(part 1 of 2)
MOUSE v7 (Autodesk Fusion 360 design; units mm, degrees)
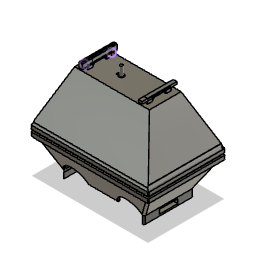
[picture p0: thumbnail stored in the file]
work_plane "WorkPlane1" AlongDistance 0
sketch "Sketch1" plane through (0, 0, 0) normal (0, 1, 0) x axis (1, 0, 0)
work_plane "WorkPlane1" AlongDistance 0
sketch "Sketch1" plane through (0, 0, 0) normal (0, 1, 0) x axis (1, 0, 0)
  line L1 (-450, 0) -> (0, 0)
  line L2 (0, 275) -> (0, 0)
  line L3 (-450, 0) -> (0, 0)
  line L4 (-450, 275) -> (-450, 0)
  line L5 (0, 275) -> (-450, 275)
  line L6 (0, 0) -> (0, 275)
  point P1 (0, 0)
  point P2 (0, 0)
  point P4 (0, 0)
  point P6 (0, 0)
  point P3 (-450, 0)
  point P5 (0, 275)
  coincident P1 P2
  horizontal L1
  coincident P1 P4
  perpendicular L1 L2
  horizontal L3
  vertical L4
  horizontal L5
  vertical L6
  coincident P1 P6
  dimension "d3" distance P2 P3 = 450
  dimension "d4" distance P4 P5 = 275
extrude "Extrude1" new body sketch "Sketch1" along normal blind 10
work_plane "WorkPlane2" AlongDistance 150
sketch "Sketch2" plane through (0, 160, 0) normal (0, 1, 0) x axis (1, 0, 0)
  line L1 (-450, 275) -> (0, 275)
  line L2 (-450, 0) -> (-450, 275)
  line L3 (0, 137.5) -> (-450, 137.5)
  line L4 (-225, 0) -> (-225, 275)
  line L5 (-537.5, -62.5) -> (87.5, -62.5)
  line L6 (-537.5, 337.5) -> (-537.5, -62.5)
  line L7 (87.5, 337.5) -> (-537.5, 337.5)
  line L8 (87.5, -62.5) -> (87.5, 337.5)
  line L9 (-537.5, 337.5) -> (87.5, -62.5)
  line L10 (87.5, 337.5) -> (-537.5, -62.5)
  point P5 (-450, 137.5)
  point P7 (-225, 275)
  point P13 (-225, 137.5)
  point P11 (-537.5, 337.5)
  point P12 (87.5, 337.5)
  point P10 (-537.5, -62.5)
  horizontal L1
  perpendicular L1 L2
  midpoint L2 P5
  perpendicular L2 L3
  midpoint L1 P7
  perpendicular L3 L4
  horizontal L5
  perpendicular L5 L6
  parallel L5 L7
  parallel L6 L8
  coincident L9 P13
  coincident L10 P13
  midpoint L4 P13
  dimension "d8" distance P11 P12 = 625
  dimension "d9" distance P10 P11 = 400
loft "Loft1" sketch "Sketch2"
sketch "Sketch3" plane through (0, 160, 0) normal (0, 1, 0) x axis (-1, 0, 0)
  line L1 (-87.5, -337.5) -> (-87.5, 62.5)
  line L2 (537.5, -337.5) -> (-87.5, -337.5)
  line L3 (537.5, 62.5) -> (537.5, -337.5)
  line L4 (-87.5, 62.5) -> (537.5, 62.5)
  line L5 (537.5, 62.5) -> (-87.5, 62.5)
  line L6 (537.5, 62.5) -> (537.5, -337.5)
  line L7 (-87.5, -137.5) -> (537.5, -137.5)
  line L8 (225, -337.5) -> (225, 62.5)
  line L9 (550, 75) -> (-100, 75)
  line L10 (550, -350) -> (550, 75)
  line L11 (-100, -350) -> (550, -350)
  line L12 (-100, 75) -> (-100, -350)
  line L13 (550, -350) -> (-100, 75)
  line L14 (-100, -350) -> (550, 75)
  point P2 (-87.5, 62.5)
  point P6 (-87.5, 62.5)
  point P5 (537.5, 62.5)
  point P7 (537.5, 62.5)
  point P4 (537.5, -337.5)
  point P8 (537.5, -337.5)
  point P9 (537.5, -137.5)
  point P10 (-87.5, -137.5)
  point P11 (225, 62.5)
  point P12 (225, -337.5)
  point P17 (225, -137.5)
  point P15 (550, -350)
  point P16 (-100, -350)
  point P14 (550, 75)
  coincident P2 P6
  coincident P5 P7
  coincident P4 P8
  midpoint L6 P9
  midpoint L1 P10
  midpoint L5 P11
  midpoint L2 P12
  horizontal L9
  perpendicular L9 L10
  parallel L9 L11
  parallel L10 L12
  coincident L13 P17
  coincident L14 P17
  midpoint L8 P17
  dimension "d10" distance P15 P16 = 650
  dimension "d11" distance P14 P15 = 425
extrude "Extrude2" new body sketch "Sketch3" profile of L1 L2 L3 L4 L5 L6 L9 L10 L11 L12 along normal blind 20
extrude "Extrude3" add of existing geometry blind 25
extrude "Extrude4" add of existing geometry blind 25
extrude "Extrude5" add of existing geometry blind 25
extrude "Extrude6" add of existing geometry blind 25
shell "Shell1" innerThickness 10
work_plane "WorkPlane3" AlongDistance 0
sketch "Sketch4" plane through (0, 0, -275) normal (0, 0, -1) x axis (-1, 0, 0)
  line L1 (450, 0) -> (0, 0)
  line L2 (375, 0) -> (225, 0)
  line L3 (75, 0) -> (225, 0)
  circle C1 centre (375, 0) radius 67.5
  circle C2 centre (75, 0) radius 67.5
  point P1 (0, 0)
  point P2 (0, 0)
  point P4 (225, 0)
  point P5 (375, 0)
  point P6 (375, 0)
  point P7 (75, 0)
  point P8 (75, 0)
  coincident P1 P2
  horizontal L1
  midpoint L1 P4
  parallel L1 L2
  coincident P5 P6
  parallel L1 L3
  coincident P7 P8
  dimension "d24" distance P4 P5 = 150
  dimension "d25" diameter C1 = 135
  dimension "d26" distance P4 P7 = 150
  dimension "d27" diameter C2 = 135
extrude "Extrude7" cut sketch "Sketch4" distance -330
extrude "Extrude8" cut of existing geometry blind -130
extrude "Extrude9" add of existing geometry blind 30
sketch "Sketch5" plane through (0, 0, 0) normal (1, 0, 0) x axis (0, 0, -1)
  line L1 (275, 10) -> (275, -30)
  line L2 (0, 10) -> (275, 10)
  line L3 (0, -30) -> (0, 10)
  line L4 (275, -30) -> (0, -30)
  line L5 (197.5, -30) -> (137.5, -30)
  line L6 (77.5, -30) -> (137.5, -30)
  line L7 (197.5, 10) -> (197.5, -30)
  line L8 (77.5, 10) -> (77.5, -30)
  line L9 (197.5, 10) -> (77.5, 10)
  point P6 (137.5, -30)
  point P9 (197.5, 10)
  point P10 (77.5, 10)
  point P7 (197.5, -30)
  point P8 (77.5, -30)
  midpoint L4 P6
  parallel L4 L5
  parallel L4 L6
  coincident L2 P9
  perpendicular L2 L7
  coincident L2 P10
  perpendicular L2 L8
  dimension "d34" distance P6 P7 = 60
  dimension "d35" distance P6 P8 = 60
extrude "Extrude10" add sketch "Sketch5" profile of L2 L4 L5 L6 L7 L8 L9 against normal blind 30
sketch "Sketch6" plane through (-450, 0, 0) normal (-1, 0, 0) x axis (0, 0, 1)
  line L1 (0, 10) -> (0, -30)
  line L2 (-275, 10) -> (0, 10)
  line L3 (-275, -30) -> (-275, 10)
  line L4 (0, -30) -> (-275, -30)
  line L5 (0, -30) -> (-275, -30)
  line L6 (-77.5, -30) -> (-137.5, -30)
  line L7 (-197.5, -30) -> (-137.5, -30)
  line L8 (-197.5, -30) -> (-77.5, -30)
  line L9 (-197.5, 10) -> (-197.5, -30)
  line L10 (-77.5, 10) -> (-197.5, 10)
  line L11 (-77.5, -30) -> (-77.5, 10)
  point P5 (-275, -30)
  point P6 (-275, -30)
  point P2 (0, -30)
  point P7 (0, -30)
  point P8 (-137.5, -30)
  point P12 (-197.5, 10)
  point P9 (-77.5, -30)
  point P10 (-197.5, -30)
  coincident P5 P6
  coincident P2 P7
  midpoint L5 P8
  perpendicular L1 L6
  parallel L5 L7
  horizontal L8
  vertical L9
  horizontal L10
  vertical L11
  coincident L2 P12
  dimension "d38" distance P8 P9 = 60
  dimension "d39" distance P8 P10 = 60
extrude "Extrude11" add sketch "Sketch6" profile of L2 L4 L5 L6 L7 L8 L9 L10 L11 against normal blind 40
extrude "Extrude12" add of existing geometry blind 10
sketch "Sketch7" plane through (0, 0, 0) normal (1, 0, 0) x axis (0, 0, -1)
  line L1 (275, -30) -> (0, -30)
  line L2 (275, 10) -> (275, -30)
  line L3 (0, 10) -> (275, 10)
  line L4 (0, -30) -> (0, 10)
  line L5 (187.5, -30) -> (137.5, -30)
  line L6 (87.5, -30) -> (137.5, -30)
  line L7 (87.5, -30) -> (187.5, -30)
  line L8 (87.5, 10) -> (87.5, -30)
  line L9 (187.5, 10) -> (87.5, 10)
  line L10 (187.5, -30) -> (187.5, 10)
  line L11 (87.5, -20) -> (87.5, -30)
  line L12 (187.5, -20) -> (87.5, -20)
  line L13 (87.5, 0) -> (87.5, 10)
  line L14 (187.5, 0) -> (87.5, 0)
  point P6 (137.5, -30)
  point P10 (87.5, 10)
  point P13 (187.5, -20)
  point P15 (187.5, 0)
  point P7 (187.5, -30)
  point P8 (87.5, -30)
  point P12 (87.5, -20)
  point P14 (87.5, 0)
  midpoint L1 P6
  parallel L1 L5
  parallel L1 L6
  horizontal L7
  vertical L8
  horizontal L9
  vertical L10
  coincident L3 P10
  perpendicular L6 L11
  coincident L10 P13
  perpendicular L10 L12
  perpendicular L9 L13
  coincident L10 P15
  perpendicular L10 L14
  dimension "d44" distance P6 P7 = 50
  dimension "d45" distance P6 P8 = 50
  dimension "d46" distance P8 P12 = 10
  dimension "d47" distance P10 P14 = 10
extrude "Extrude13" cut sketch "Sketch7" profile of L8 L10 L12 L14 against normal blind 35
extrude "Extrude14" cut of existing geometry blind -450
sketch "Sketch8" plane through (-40, 0, 0) normal (-1, 0, 0) x axis (0, 0, 1)
  line L1 (-187.5, 0) -> (-187.5, -20)
  line L2 (-87.5, 0) -> (-187.5, 0)
  line L3 (-87.5, -20) -> (-87.5, 0)
  line L4 (-187.5, -20) -> (-87.5, -20)
  line L5 (-77.5, -30) -> (-197.5, -30)
  line L6 (-77.5, 10) -> (-77.5, -30)
  line L7 (-197.5, 10) -> (-77.5, 10)
  line L8 (-197.5, -30) -> (-197.5, 10)
  line L9 (-77.5, 10) -> (-197.5, 10)
  line L10 (-77.5, -30) -> (-77.5, 10)
  line L11 (-197.5, -30) -> (-77.5, -30)
  line L12 (-197.5, 10) -> (-197.5, -30)
  point P7 (-77.5, -30)
  point P12 (-77.5, -30)
  point P9 (-197.5, 10)
  point P10 (-197.5, 10)
  horizontal L9
  vertical L10
  horizontal L11
  vertical L12
  coincident P7 P12
  coincident P9 P10
extrude "Extrude15" add sketch "Sketch8" profile of L1 L2 L3 L4 against normal blind 5
sketch "Sketch9" plane through (-410, 0, 0) normal (1, 0, 0) x axis (0, 0, -1)
  line L1 (187.5, -20) -> (187.5, 0)
  line L2 (87.5, -20) -> (187.5, -20)
  line L3 (87.5, 0) -> (87.5, -20)
  line L4 (187.5, 0) -> (87.5, 0)
  line L5 (77.5, 10) -> (197.5, 10)
  line L6 (77.5, -30) -> (77.5, 10)
  line L7 (197.5, -30) -> (77.5, -30)
  line L8 (197.5, 10) -> (197.5, -30)
  line L9 (197.5, 10) -> (77.5, 10)
  line L10 (197.5, -30) -> (197.5, 10)
  line L11 (77.5, -30) -> (197.5, -30)
  line L12 (77.5, 10) -> (77.5, -30)
  point P9 (197.5, -30)
  point P12 (197.5, -30)
  point P7 (77.5, 10)
  point P10 (77.5, 10)
  horizontal L9
  vertical L10
  horizontal L11
  vertical L12
  coincident P9 P12
  coincident P7 P10
extrude "Extrude16" add sketch "Sketch9" profile of L1 L2 L3 L4 against normal blind 5
extrude "Extrude17" cut of existing geometry blind -325
fillet "Fillet1" radius 12.5
fillet "Fillet2" radius 37.5
fillet "Fillet3" radius 4
fillet "Fillet4" radius 4
fillet "Fillet5" radius 8
work_plane "WorkPlane2" AlongDistance 0
sketch "Sketch3" plane through (-35, 0, 0) normal (1, 0, 0) x axis (0, 0, -1)
  line L1 (87, -22) -> (188, -22)
  line L2 (87, 2) -> (87, -22)
  line L3 (188, 2) -> (87, 2)
  line L4 (188, -22) -> (188, 2)
  line L5 (87, 2) -> (188, -22)
  line L6 (188, 2) -> (87, -22)
  point P6 (137.5, -10)
  horizontal L1
  perpendicular L1 L2
  parallel L1 L3
  parallel L2 L4
  coincident L5 P6
  coincident L6 P6
extrude "Extrude18" cut sketch "Sketch3" profile of L1 L2 L3 L4 along normal blind 49
extrude "Extrude19" cut blind 46
sketch "Sketch4" plane through (-35, 0, 0) normal (1, 0, 0) x axis (0, 0, -1)
  line L1 (87, 2) -> (188, 2)
  line L2 (87, -22) -> (87, 2)
  line L3 (188, -22) -> (87, -22)
  line L4 (188, 2) -> (188, -22)
  line L5 (188, 2) -> (87, 2)
  line L6 (87, -22) -> (188, -22)
  line L7 (137.5, -22) -> (137.5, 2)
  line L8 (188, -10) -> (87, -10)
  line L9 (145.22, -10) -> (139.1, -10)
  line L10 (137.5, -10) -> (146.82, -10)
  line L11 (156.14, -10) -> (146.82, -10)
  line L12 (165.46, -10) -> (156.14, -10)
  line L13 (174.78, -10) -> (165.46, -10)
  line L14 (184.1, -10) -> (174.78, -10)
  line L15 (137.5, -0.68) -> (137.5, -10)
  line L16 (146.82, -0.68) -> (146.82, -10)
  line L17 (156.14, -0.68) -> (156.14, -10)
  line L18 (165.46, -0.68) -> (165.46, -10)
  line L19 (174.78, -0.68) -> (174.78, -10)
  line L20 (184.1, -0.68) -> (184.1, -10)
  circle C1 centre (137.5, -10) radius 1.6
  circle C2 centre (146.82, -10) radius 1.6
  circle C3 centre (156.14, -10) radius 1.6
  circle C4 centre (165.46, -10) radius 1.6
  circle C5 centre (174.78, -10) radius 1.6
  circle C6 centre (184.1, -10) radius 1.6
  circle C7 centre (137.5, -0.68) radius 1.6
  circle C8 centre (146.82, -0.68) radius 1.6
  circle C9 centre (156.14, -0.68) radius 1.6
  circle C10 centre (165.46, -0.68) radius 1.6
  circle C11 centre (174.78, -0.68) radius 1.6
  circle C12 centre (184.1, -0.68) radius 1.6
  point P3 (87, 2)
  point P6 (87, 2)
  point P2 (188, 2)
  point P7 (188, 2)
  point P5 (188, -22)
  point P8 (188, -22)
  point P4 (87, -22)
  point P9 (87, -22)
  point P10 (137.5, 2)
  point P11 (137.5, -22)
  point P12 (87, -10)
  point P13 (188, -10)
  point P14 (137.5, -10)
  point P15 (139.1, -10)
  point P16 (145.22, -10)
  point P17 (146.82, -10)
  point P18 (146.82, -10)
  point P19 (137.5, -10)
  point P20 (146.82, -10)
  point P21 (156.14, -10)
  point P22 (156.14, -10)
  point P23 (156.14, -10)
  point P24 (165.46, -10)
  point P25 (165.46, -10)
  point P26 (165.46, -10)
  point P27 (174.78, -10)
  point P28 (174.78, -10)
  point P29 (174.78, -10)
  point P30 (184.1, -10)
  point P31 (184.1, -10)
  point P32 (137.5, -10)
  point P33 (137.5, -0.68)
  point P34 (137.5, -0.68)
  point P35 (146.82, -10)
  point P36 (146.82, -0.68)
  point P37 (146.82, -0.68)
  point P38 (156.14, -10)
  point P39 (156.14, -0.68)
  point P40 (156.14, -0.68)
  point P41 (165.46, -10)
  point P42 (165.46, -0.68)
  point P43 (165.46, -0.68)
  point P44 (174.78, -10)
  point P45 (174.78, -0.68)
  point P46 (174.78, -0.68)
  point P47 (184.1, -10)
  point P48 (184.1, -0.68)
  point P49 (184.1, -0.68)
  coincident P3 P6
  coincident P2 P7
  coincident P5 P8
  coincident P4 P9
  midpoint L5 P10
  midpoint L6 P11
  midpoint L2 P12
  midpoint L4 P13
  midpoint L7 P14
  coincident C1 P15
  coincident L8 P15
  parallel L8 L9
  coincident P16 C2
  coincident P17 P18
  coincident P14 P19
  coincident P17 P20
  parallel L8 L11
  coincident P21 P22
  coincident P22 P23
  parallel L8 L12
  coincident P24 P25
  coincident P25 P26
  parallel L8 L13
  coincident P27 P28
  coincident P28 P29
  parallel L8 L14
  coincident P30 P31
  coincident P14 P32
  perpendicular L10 L15
  coincident P33 P34
  coincident P17 P35
  perpendicular L11 L16
  coincident P36 P37
  coincident P22 P38
  perpendicular L8 L17
  coincident P39 P40
  coincident P25 P41
  perpendicular L13 L18
  coincident P42 P43
  coincident P28 P44
  perpendicular L8 L19
  coincident P45 P46
  coincident P31 P47
  perpendicular L14 L20
  coincident P48 P49
  dimension "d86" diameter C1 = 3.2
  dimension "d87" distance P15 P16 = 6.12
  dimension "d88" diameter C2 = 3.2
  dimension "d89" distance P20 P21 = 9.32
  dimension "d90" diameter C3 = 3.2
  dimension "d91" distance P23 P24 = 9.32
  dimension "d92" diameter C4 = 3.2
  dimension "d93" distance P26 P27 = 9.32
  dimension "d94" diameter C5 = 3.2
  dimension "d95" distance P29 P30 = 9.32
  dimension "d96" diameter C6 = 3.2
  dimension "d97" distance P32 P33 = 9.32
  dimension "d98" diameter C7 = 3.2
  dimension "d99" distance P35 P36 = 9.32
  dimension "d100" diameter C8 = 3.2
  dimension "d101" distance P38 P39 = 9.32
  dimension "d102" diameter C9 = 3.2
  dimension "d103" distance P41 P42 = 9.32
  dimension "d104" diameter C10 = 3.2
  dimension "d105" distance P44 P45 = 9.32
  dimension "d106" diameter C11 = 3.2
  dimension "d107" distance P47 P48 = 9.32
  dimension "d108" diameter C12 = 3.2
extrude "Extrude20" cut sketch "Sketch4" profile of L7 L8 C1 C2 L10 L11 C3 L12 C4 L13 C5 L14 C6 L15 C7 L16 C8 L17 C9 L18 C10 L19 C11 L20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 against normal blind 500
mirror "Mirror1" mirrorStitchTolerance 0.1
position "Position1"
mirror "Mirror2" mirrorStitchTolerance 0.1
sketch "Sketch5" plane through (-450, 0, 0) normal (-1, 0, 0) x axis (0, 0, 1)
  line L1 (-118.3247, -31.4358) -> (-111.9013, -31.4358)
  line L2 (-127.6447, -31.4358) -> (-121.2213, -31.4358)
  line L3 (-136.9647, -31.4358) -> (-130.5413, -31.4358)
  line L4 (-146.3247, -31.4358) -> (-139.9013, -31.4358)
  line L5 (-155.6447, -31.4358) -> (-149.2213, -31.4358)
  line L6 (-164.9647, -31.4358) -> (-158.5413, -31.4358)
  line L7 (-174.2847, -31.4358) -> (-167.8613, -31.4358)
  line L8 (-183.6047, -31.4358) -> (-177.1813, -31.4358)
  line L9 (-188.453, -31.4358) -> (-186.5013, -31.4358)
  line L10 (-188.453, -11.4358) -> (-188.453, -31.4358)
  line L11 (-186.5013, -11.4358) -> (-188.453, -11.4358)
  line L12 (-177.1813, -11.4358) -> (-183.6047, -11.4358)
  line L13 (-167.8613, -11.4358) -> (-174.2847, -11.4358)
  line L14 (-158.5413, -11.4358) -> (-164.9647, -11.4358)
  line L15 (-149.2213, -11.4358) -> (-155.6447, -11.4358)
  line L16 (-139.9013, -11.4358) -> (-146.3247, -11.4358)
  line L17 (-130.5413, -11.4358) -> (-136.9647, -11.4358)
  line L18 (-121.2213, -11.4358) -> (-127.6447, -11.4358)
  line L19 (-111.9013, -11.4358) -> (-118.3247, -11.4358)
  line L20 (-102.5813, -11.4358) -> (-109.0047, -11.4358)
  line L21 (-93.2613, -11.4358) -> (-99.6847, -11.4358)
  line L22 (-88.453, -11.4358) -> (-90.3647, -11.4358)
  line L23 (-88.453, -31.4358) -> (-88.453, -11.4358)
  line L24 (-90.3647, -31.4358) -> (-88.453, -31.4358)
  line L25 (-99.6847, -31.4358) -> (-93.2613, -31.4358)
  line L26 (-109.0047, -31.4358) -> (-102.5813, -31.4358)
  line L27 (-267.953, -41.4358) -> (-267.953, -0.8983)
  line L28 (-8.953, -41.4358) -> (-267.953, -41.4358)
  line L29 (-8.953, -0.8983) -> (-8.953, -41.4358)
  line L30 (-265.0356, -1.4358) -> (-11.8703, -1.4358)
  line L31 (-188.5924, -32.6831) -> (-88.2747, -32.6831)
  line L32 (-188.5924, -10.1699) -> (-188.5924, -32.6831)
  line L33 (-88.2747, -10.1699) -> (-188.5924, -10.1699)
  line L34 (-88.2747, -32.6831) -> (-88.2747, -10.1699)
  line L35 (-188.5924, -10.1699) -> (-88.2747, -32.6831)
  line L36 (-88.2747, -10.1699) -> (-188.5924, -32.6831)
  arc A1 centre (-110.453, -30.7558) radius 1.6 clockwise from (-109.0047, -31.4358) to (-111.9013, -31.4358)
  arc A2 centre (-119.773, -30.7558) radius 1.6 clockwise from (-118.3247, -31.4358) to (-121.2213, -31.4358)
  arc A3 centre (-129.093, -30.7558) radius 1.6 clockwise from (-127.6447, -31.4358) to (-130.5413, -31.4358)
  arc A4 centre (-138.413, -30.7558) radius 1.6 clockwise from (-136.9647, -31.4358) to (-138.433, -32.3556)
  arc A5 centre (-138.453, -30.7558) radius 1.6 clockwise from (-138.433, -32.3556) to (-139.9013, -31.4358)
  arc A6 centre (-147.773, -30.7558) radius 1.6 clockwise from (-146.3247, -31.4358) to (-149.2213, -31.4358)
  arc A7 centre (-157.093, -30.7558) radius 1.6 clockwise from (-155.6447, -31.4358) to (-158.5413, -31.4358)
  arc A8 centre (-166.413, -30.7558) radius 1.6 clockwise from (-164.9647, -31.4358) to (-167.8613, -31.4358)
  arc A9 centre (-175.733, -30.7558) radius 1.6 clockwise from (-174.2847, -31.4358) to (-177.1813, -31.4358)
  arc A10 centre (-185.053, -30.7558) radius 1.6 clockwise from (-183.6047, -31.4358) to (-186.5013, -31.4358)
  arc A11 centre (-185.053, -12.1158) radius 1.6 clockwise from (-186.5013, -11.4358) to (-183.6047, -11.4358)
  arc A12 centre (-175.733, -12.1158) radius 1.6 clockwise from (-177.1813, -11.4358) to (-174.2847, -11.4358)
  arc A13 centre (-166.413, -12.1158) radius 1.6 clockwise from (-167.8613, -11.4358) to (-164.9647, -11.4358)
  arc A14 centre (-157.093, -12.1158) radius 1.6 clockwise from (-158.5413, -11.4358) to (-155.6447, -11.4358)
  arc A15 centre (-147.773, -12.1158) radius 1.6 clockwise from (-149.2213, -11.4358) to (-146.3247, -11.4358)
  arc A16 centre (-138.453, -12.1158) radius 1.6 clockwise from (-139.9013, -11.4358) to (-138.433, -10.5159)
  arc A17 centre (-138.413, -12.1158) radius 1.6 clockwise from (-138.433, -10.5159) to (-136.9647, -11.4358)
  arc A18 centre (-129.093, -12.1158) radius 1.6 clockwise from (-130.5413, -11.4358) to (-127.6447, -11.4358)
  arc A19 centre (-119.773, -12.1158) radius 1.6 clockwise from (-121.2213, -11.4358) to (-118.3247, -11.4358)
  arc A20 centre (-110.453, -12.1158) radius 1.6 clockwise from (-111.9013, -11.4358) to (-109.0047, -11.4358)
  arc A21 centre (-101.133, -12.1158) radius 1.6 clockwise from (-102.5813, -11.4358) to (-99.6847, -11.4358)
  arc A22 centre (-91.813, -12.1158) radius 1.6 clockwise from (-93.2613, -11.4358) to (-90.3647, -11.4358)
  arc A23 centre (-91.813, -30.7558) radius 1.6 clockwise from (-90.3647, -31.4358) to (-93.2613, -31.4358)
  arc A24 centre (-101.133, -30.7558) radius 1.6 clockwise from (-99.6847, -31.4358) to (-102.5813, -31.4358)
  closed curve K1 centre (-4.158, 23.3722)
  closed curve K2 centre (-272.748, 23.3722)
  circle C1 centre (-138.4336, -21.4265) radius 1.6196
  point P89 (-138.4336, -21.4265)
  point P84 (-138.4336, -21.4265)
  horizontal L31
  perpendicular L31 L32
  parallel L31 L33
  parallel L32 L34
  coincident L35 P89
  coincident L36 P89
  coincident P84 P89
extrude "Extrude21" cut sketch "Sketch5" profile of A1 L1 A2 L2 A3 L3 A4 A5 L4 A6 L5 A7 L6 A8 L7 A9 L8 A10 L9 L10 L11 A11 L12 A12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 against normal blind 35
fillet "Fillet6" radius 30
fillet "Fillet7" radius 62.5
extrude "Extrude22" add of existing geometry blind 1
sketch "Sketch6" plane through (0, 168.5642, 0) normal (0, 1, 0) x axis (-1, 0, 0)
  line L1 (546, -350.953) -> (-96, -350.953)
  line L2 (550, 70.047) -> (550, -346.953)
  line L3 (-96, 74.047) -> (546, 74.047)
  line L4 (-100, -346.953) -> (-100, 70.047)
  line L5 (-62.5, 36.547) -> (-62.5, -313.453)
  line L6 (512.5, 36.547) -> (-62.5, 36.547)
  line L7 (512.5, -313.453) -> (512.5, 36.547)
  line L8 (-62.5, -313.453) -> (512.5, -313.453)
  line L9 (-98.8284, 72.8754) -> (-62.5, 36.547)
  line L10 (548.8284, -349.7814) -> (512.5, -313.453)
  line L11 (548.8284, 72.8754) -> (512.5, 36.547)
  line L12 (-98.8284, -349.7814) -> (-62.5, -313.453)
  line L13 (-62.5, -350.953) -> (-80.6642, -331.6172)
  line L14 (-62.5, 74.047) -> (-80.6642, 54.7112)
  line L15 (512.5, 74.047) -> (530.6642, 54.7112)
  line L16 (512.5, -350.953) -> (530.6642, -331.6172)
  arc A1 centre (-96, -346.953) radius 4 clockwise from (-96, -350.953) to (-100, -346.953)
  arc A2 centre (546, -346.953) radius 4 clockwise from (550, -346.953) to (546, -350.953)
  arc A3 centre (546, 70.047) radius 4 clockwise from (546, 74.047) to (550, 70.047)
  arc A4 centre (-96, 70.047) radius 4 clockwise from (-100, 70.047) to (-96, 74.047)
  circle C1 centre (-80.6642, -331.6172) radius 7.5
  circle C2 centre (-80.6642, 54.7112) radius 7.5
  circle C3 centre (530.6642, 54.7112) radius 7.5
  circle C4 centre (530.6642, -331.6172) radius 7.5
  point P15 (-62.5, 36.547)
  point P18 (-62.5, 36.547)
  point P19 (-98.8284, 72.8754)
  point P17 (512.5, -313.453)
  point P20 (512.5, -313.453)
  point P21 (548.8284, -349.7814)
  point P16 (512.5, 36.547)
  point P22 (512.5, 36.547)
  point P23 (548.8284, 72.8754)
  point P14 (-62.5, -313.453)
  point P24 (-62.5, -313.453)
  point P25 (-98.8284, -349.7814)
  point P26 (-80.6642, -331.6172)
  point P27 (-62.5, -350.953)
  point P28 (-80.6642, -331.6172)
  point P29 (-80.6642, 54.7112)
  point P30 (-62.5, 74.047)
  point P31 (-80.6642, 54.7112)
  point P32 (530.6642, 54.7112)
  point P33 (512.5, 74.047)
  point P34 (530.6642, 54.7112)
  point P35 (530.6642, -331.6172)
  point P36 (512.5, -350.953)
  point P37 (530.6642, -331.6172)
  coincident P15 P18
  midpoint A4 P19
  coincident P17 P20
  midpoint A2 P21
  coincident P16 P22
  midpoint A3 P23
  coincident P14 P24
  midpoint A1 P25
  midpoint L12 P26
  coincident L1 P27
  coincident P26 P28
  midpoint L9 P29
  coincident L3 P30
  coincident P29 P31
  midpoint L11 P32
  coincident L3 P33
  coincident P32 P34
  midpoint L10 P35
  coincident L1 P36
  coincident P35 P37
  dimension "d125" diameter C1 = 15
  dimension "d126" diameter C2 = 15
  dimension "d127" diameter C3 = 15
  dimension "d128" diameter C4 = 15
extrude "Extrude23" add sketch "Sketch6" profile of L9 L10 L11 L12 L13 C1 L14 C2 L15 C3 L16 C4 along normal blind 15
work_plane "WorkPlane1" AlongDistance 0
sketch "Sketch1" plane through (0, 168.5642, 0) normal (0, 1, 0) x axis (1, 0, 0)
  line L1 (-512.5, 313.45) -> (62.5, 313.45)
  line L2 (-512.5, -36.5) -> (-512.5, 313.45)
  line L3 (62.5, -36.5) -> (-512.5, -36.5)
  line L4 (62.5, 313.45) -> (62.5, -36.5)
  line L5 (100, -74) -> (-550, -74)
  line L6 (100, 351) -> (100, -74)
  line L7 (-550, 351) -> (100, 351)
  line L8 (-550, -74) -> (-550, 351)
  horizontal L1
  vertical L2
  horizontal L3
  vertical L4
  horizontal L5
  vertical L6
  horizontal L7
  vertical L8
extrude "Extrude1" new body sketch "Sketch1" along normal blind 20
sketch "Sketch2" plane through (0, 188.5642, 0) normal (0, 1, 0) x axis (-1, 0, 0)
  line L1 (-62.5, 36.5) -> (-62.5, -313.45)
  line L2 (512.5, 36.5) -> (-62.5, 36.5)
  line L3 (512.5, -313.45) -> (512.5, 36.5)
  line L4 (-62.5, -313.45) -> (512.5, -313.45)
  line L5 (550, 74) -> (550, -351)
  line L6 (-100, 74) -> (550, 74)
  line L7 (-100, -351) -> (-100, 74)
  line L8 (550, -351) -> (-100, -351)
  line L9 (-100, 74) -> (-62.5, 36.5)
  line L10 (-62.5, 74) -> (-81.25, 55.25)
  circle C1 centre (-81.25, 55.25) radius 7.5
  point P3 (-62.5, 36.5)
  point P10 (-62.5, 36.5)
  point P8 (-100, 74)
  point P11 (-100, 74)
  point P12 (-81.25, 55.25)
  point P13 (-62.5, 74)
  point P14 (-81.25, 55.25)
  coincident P3 P10
  coincident P8 P11
  midpoint L9 P12
  coincident L6 P13
  perpendicular L9 L10
  coincident P12 P14
  dimension "d134" diameter C1 = 15
extrude "Extrude24" cut sketch "Sketch2" profile of L9 L10 C1 against normal blind 20
sketch "Sketch3" plane through (0, 188.5642, 0) normal (0, 1, 0) x axis (-1, 0, 0)
  line L1 (-62.5, 36.5) -> (-62.5, -313.45)
  line L2 (512.5, 36.5) -> (-62.5, 36.5)
  line L3 (512.5, -313.45) -> (512.5, 36.5)
  line L4 (-62.5, -313.45) -> (512.5, -313.45)
  line L5 (550, 74) -> (550, -351)
  line L6 (-100, 74) -> (550, 74)
  line L7 (-100, -351) -> (-100, 74)
  line L8 (550, -351) -> (-100, -351)
  circle C1 centre (-81.25, 55.25) radius 7.5
  circle C2 centre (-81.25, 55.25) radius 7.5
  concentric C1 C2
extrude "Extrude3" add sketch "Sketch3" profile of C1 C2 against normal blind 5
sketch "Sketch4" plane through (0, 188.5642, 0) normal (0, 1, 0) x axis (-1, 0, 0)
  line L1 (-62.5, 36.5) -> (-62.5, -313.45)
  line L2 (512.5, 36.5) -> (-62.5, 36.5)
  line L3 (512.5, -313.45) -> (512.5, 36.5)
  line L4 (-62.5, -313.45) -> (512.5, -313.45)
  line L5 (550, 74) -> (550, -351)
  line L6 (-100, 74) -> (550, 74)
  line L7 (-100, -351) -> (-100, 74)
  line L8 (550, -351) -> (-100, -351)
  line L9 (550, 74) -> (512.5, 36.5)
  line L10 (550, 36.5) -> (531.25, 55.25)
  circle C1 centre (531.25, 55.25) radius 7.5
  point P4 (512.5, 36.5)
  point P10 (512.5, 36.5)
  point P7 (550, 74)
  point P11 (550, 74)
  point P12 (531.25, 55.25)
  point P13 (550, 36.5)
  point P14 (531.25, 55.25)
  coincident P4 P10
  coincident P7 P11
  midpoint L9 P12
  coincident L5 P13
  perpendicular L9 L10
  coincident P12 P14
  dimension "d141" diameter C1 = 15
extrude "Extrude25" cut sketch "Sketch4" profile of L9 L10 C1 against normal blind 20
sketch "Sketch5" plane through (0, 188.5642, 0) normal (0, 1, 0) x axis (-1, 0, 0)
  line L1 (-62.5, 36.5) -> (-62.5, -313.45)
  line L2 (512.5, 36.5) -> (-62.5, 36.5)
  line L3 (512.5, -313.45) -> (512.5, 36.5)
  line L4 (-62.5, -313.45) -> (512.5, -313.45)
  line L5 (550, 74) -> (550, -351)
  line L6 (-100, 74) -> (550, 74)
  line L7 (-100, -351) -> (-100, 74)
  line L8 (550, -351) -> (-100, -351)
  circle C1 centre (531.25, 55.25) radius 7.5
  circle C2 centre (531.25, 55.25) radius 7.5
  concentric C1 C2
extrude "Extrude5" add sketch "Sketch5" profile of C1 C2 against normal blind 5
sketch "Sketch6" plane through (0, 188.5642, 0) normal (0, 1, 0) x axis (-1, 0, 0)
  line L1 (-62.5, 36.5) -> (-62.5, -313.45)
  line L2 (512.5, 36.5) -> (-62.5, 36.5)
  line L3 (512.5, -313.45) -> (512.5, 36.5)
  line L4 (-62.5, -313.45) -> (512.5, -313.45)
  line L5 (550, 74) -> (550, -351)
  line L6 (-100, 74) -> (550, 74)
  line L7 (-100, -351) -> (-100, 74)
  line L8 (550, -351) -> (-100, -351)
  line L9 (-100, -351) -> (-62.5, -313.45)
  circle C1 centre (-81.25, -332.225) radius 7.5
  point P2 (-62.5, -313.45)
  point P10 (-62.5, -313.45)
  point P9 (-100, -351)
  point P11 (-100, -351)
  point P12 (-81.25, -332.225)
  coincident P2 P10
  coincident P9 P11
  midpoint L9 P12
  dimension "d148" diameter C1 = 15
extrude "Extrude26" cut sketch "Sketch6" profile of L9 C1 against normal blind 20
sketch "Sketch7" plane through (0, 188.5642, 0) normal (0, 1, 0) x axis (-1, 0, 0)
  line L1 (-62.5, 36.5) -> (-62.5, -313.45)
  line L2 (512.5, 36.5) -> (-62.5, 36.5)
  line L3 (512.5, -313.45) -> (512.5, 36.5)
  line L4 (-62.5, -313.45) -> (512.5, -313.45)
  line L5 (550, 74) -> (550, -351)
  line L6 (-100, 74) -> (550, 74)
  line L7 (-100, -351) -> (-100, 74)
  line L8 (550, -351) -> (-100, -351)
  circle C1 centre (-81.25, -332.225) radius 7.5
  circle C2 centre (-81.25, -332.225) radius 7.5
  concentric C1 C2
extrude "Extrude7" add sketch "Sketch7" profile of C1 C2 against normal blind 5
sketch "Sketch8" plane through (0, 188.5642, 0) normal (0, 1, 0) x axis (-1, 0, 0)
  line L1 (-62.5, 36.5) -> (-62.5, -313.45)
  line L2 (512.5, 36.5) -> (-62.5, 36.5)
  line L3 (512.5, -313.45) -> (512.5, 36.5)
  line L4 (-62.5, -313.45) -> (512.5, -313.45)
  line L5 (550, 74) -> (550, -351)
  line L6 (-100, 74) -> (550, 74)
  line L7 (-100, -351) -> (-100, 74)
  line L8 (550, -351) -> (-100, -351)
  line L9 (550, -351) -> (512.5, -313.45)
  circle C1 centre (531.25, -332.225) radius 7.5
  point P5 (512.5, -313.45)
  point P10 (512.5, -313.45)
  point P6 (550, -351)
  point P11 (550, -351)
  point P12 (531.25, -332.225)
  coincident P5 P10
  coincident P6 P11
  midpoint L9 P12
  dimension "d155" diameter C1 = 15
extrude "Extrude27" cut sketch "Sketch8" profile of L9 C1 against normal blind 20
sketch "Sketch9" plane through (0, 188.5642, 0) normal (0, 1, 0) x axis (-1, 0, 0)
  line L1 (-62.5, 36.5) -> (-62.5, -313.45)
  line L2 (512.5, 36.5) -> (-62.5, 36.5)
  line L3 (512.5, -313.45) -> (512.5, 36.5)
  line L4 (-62.5, -313.45) -> (512.5, -313.45)
  line L5 (550, 74) -> (550, -351)
  line L6 (-100, 74) -> (550, 74)
  line L7 (-100, -351) -> (-100, 74)
  line L8 (550, -351) -> (-100, -351)
  circle C1 centre (531.25, -332.225) radius 7.5
  circle C2 centre (531.25, -332.225) radius 7.5
  concentric C1 C2
extrude "Extrude9" add sketch "Sketch9" profile of C1 C2 against normal blind 5
extrude "Extrude10" add of existing geometry blind 10
sketch "Sketch10" plane through (0, 168.5642, 0) normal (0, -1, 0) x axis (1, 0, 0)
  line L1 (62.5, -313.45) -> (62.5, 36.5)
  line L2 (-512.5, -313.45) -> (62.5, -313.45)
  line L3 (-512.5, 36.5) -> (-512.5, -313.45)
  line L4 (62.5, 36.5) -> (-512.5, 36.5)
  line L5 (-550, -351) -> (-550, 74)
  line L6 (100, -351) -> (-550, -351)
  line L7 (100, 74) -> (100, -351)
  line L8 (-550, 74) -> (100, 74)
  line L9 (90, 70) -> (90, 55)
  line L10 (88.7458, 55) -> (90, 55)
  line L11 (81.5273, 63.9989) -> (81.5273, 62.7449)
  line L12 (90, 63.9989) -> (81.5273, 63.9989)
  line L13 (90, -351) -> (90, 55)
  line L14 (-650, 63.9989) -> (81.5273, 63.9989)
  line L15 (-540, 36.8101) -> (-550, 36.8101)
  line L16 (-540, 90) -> (-540, 36.8101)
  line L17 (-540, -400) -> (-540, 90)
  line L18 (-492.8594, -341) -> (-492.8594, -351)
  line L19 (-570, -341) -> (-492.8594, -341)
  line L20 (-490, -341) -> (-570, -341)
  line L21 (-492.8594, -341) -> (-490, -341)
  line L22 (90, -341) -> (-492.8594, -341)
  circle C1 centre (-531.25, -332.225) radius 7.5
  circle C2 centre (81.25, -332.225) radius 7.5
  circle C3 centre (-531.25, 55.25) radius 7.5
  circle C4 centre (81.25, 55.25) radius 7.5
  point P16 (88.7458, 55)
  point P17 (81.5273, 62.7449)
  point P19 (90, 63.9989)
  point P20 (90, -351)
  point P22 (-550, 36.8101)
  point P26 (-492.8594, -351)
  point P30 (90, -341)
  point P18 (81.5273, 63.9989)
  point P23 (-540, 36.8101)
  point P27 (-492.8594, -341)
  parallel L7 L9
  coincident C4 P16
  perpendicular L9 L10
  coincident C4 P17
  perpendicular L10 L11
  coincident L9 P19
  perpendicular L9 L12
  coincident L6 P20
  perpendicular L6 L13
  perpendicular L5 L14
  coincident L5 P22
  perpendicular L5 L15
  perpendicular L15 L16
  perpendicular L6 L17
  coincident L6 P26
  perpendicular L6 L18
  perpendicular L5 L19
  perpendicular L5 L20
  perpendicular L18 L21
  coincident L13 P30
  perpendicular L13 L22
  dimension "d164" distance P17 P18 = 1.254
  dimension "d165" distance P22 P23 = 10
  dimension "d166" distance P26 P27 = 10
extrude "Extrude11" cut sketch "Sketch10" profile of L5 L6 L7 L8 L9 L12 L13 L14 L15 L16 L17 L18 L19 L20 L21 L22 against normal blind 12.5
extrude "Extrude12" add of existing geometry blind 2.5
fillet "Fillet1" radius 4
work_plane "WorkPlane5" AlongDistance 275
sketch "Sketch7" plane through (0, 476.0642, 0) normal (0, 1, 0) x axis (1, 0, 0)
  line L1 (100, 350) -> (-550, 350)
  line L2 (100, -75) -> (100, 350)
  line L3 (-550, -75) -> (100, -75)
  line L4 (-550, 350) -> (-550, -75)
  line L5 (-430.5782, 11.4851) -> (-430.5782, 263.5149)
  line L6 (-18.0464, 263.5878) -> (-18.0464, 11.4122)
  line L7 (-430.5782, 11.4851) -> (-18.0464, 263.5878)
  line L8 (-18.0464, 11.4122) -> (-430.5782, 263.5149)
  line L9 (-18.1656, 50) -> (-430.5782, 50)
  line L10 (-18.1656, 225) -> (-18.1656, 50)
  line L11 (-430.5782, 225) -> (-18.1656, 225)
  line L12 (-430.5782, 50) -> (-430.5782, 225)
  line L13 (-18.1656, 225) -> (-430.5782, 50)
  line L14 (-430.5782, 225) -> (-18.1656, 50)
  point P10 (-224.3719, 137.5)
  point P15 (-224.3719, 137.5)
  point P11 (-430.5782, 50)
  horizontal L1
  vertical L2
  horizontal L3
  vertical L4
  parallel L5 L6
  coincident L7 P10
  coincident L8 P10
  horizontal L9
  perpendicular L9 L10
  parallel L9 L11
  parallel L10 L12
  coincident L13 P15
  coincident L14 P15
  coincident L5 P11
  coincident P10 P15
sketch "Sketch8" plane through (0, 201.0642, 0) normal (0, 1, 0) x axis (-1, 0, 0)
  line L1 (-62.5, 36.5) -> (-62.5, -313.45)
  line L2 (512.5, 36.5) -> (-62.5, 36.5)
  line L3 (512.5, -313.45) -> (512.5, 36.5)
  line L4 (-62.5, -313.45) -> (512.5, -313.45)
  line L5 (-100, -347) -> (-100, 70)
  line L6 (546, -351) -> (-96, -351)
  line L7 (550, 70) -> (550, -347)
  line L8 (-96, 74) -> (546, 74)
  line L9 (-100, -350) -> (550, -350)
  line L10 (-100, 75) -> (-100, -350)
  line L11 (550, 75) -> (-100, 75)
  line L12 (550, -350) -> (550, 75)
  arc A1 centre (-96, 70) radius 4 clockwise from (-100, 70) to (-96, 74)
  arc A2 centre (-96, -347) radius 4 clockwise from (-96, -351) to (-100, -347)
  arc A3 centre (546, -347) radius 4 clockwise from (550, -347) to (546, -351)
  arc A4 centre (546, 70) radius 4 clockwise from (546, 74) to (550, 70)
  horizontal L9
  vertical L10
  horizontal L11
  vertical L12
loft "Loft1" sketch "Sketch8" + "Sketch7"
shell "Shell1" innerThickness 10
sketch "Sketch9" plane through (0, 476.0642, 0) normal (0, 1, 0) x axis (-1, 0, 0)
  line L1 (18.1656, -50) -> (430.5782, -50)
  line L2 (430.5782, -225) -> (18.1656, -225)
  line L3 (430.5782, -50) -> (430.5782, -225)
  line L4 (0, -137.5) -> (430.5782, -137.5)
  line L5 (430.5782, -202.5) -> (430.5782, -137.5)
  line L6 (430.5782, -72.5) -> (430.5782, -137.5)
  line L7 (379.7049, -202.5) -> (399.8912, -202.5)
  line L8 (379.7049, -72.5) -> (379.7049, -202.5)
  line L9 (399.8912, -72.5) -> (379.7049, -72.5)
  line L10 (399.8912, -202.5) -> (399.8912, -72.5)
  line L11 (379.7049, -90) -> (400, -90)
  line L12 (399.8912, -72.5) -> (400, -90)
  line L13 (399.8912, -185) -> (399.8912, -202.5)
  line L14 (379.7049, -185) -> (399.8912, -185)
  line L15 (18.1656, -225) -> (18.1656, -50)
  point P6 (430.5782, -137.5)
  point P15 (379.7049, -90)
  point P17 (379.7049, -185)
  point P8 (430.5782, -202.5)
  point P9 (430.5782, -72.5)
  point P10 (399.8912, -202.5)
  point P16 (399.8912, -185)
  midpoint L3 P6
  perpendicular L4 L5
  perpendicular L4 L6
  horizontal L7
  vertical L8
  horizontal L9
  vertical L10
  coincident L8 P15
  perpendicular L8 L11
  perpendicular L7 L13
  coincident L8 P17
  perpendicular L8 L14
  dimension "d175" distance P6 P8 = 65
  dimension "d176" distance P6 P9 = 65
  dimension "d177" distance P10 P16 = 17.5
extrude "Extrude13" add sketch "Sketch9" profile of L7 L8 L9 L10 L11 L13 L14 along normal blind 20
sketch "Sketch10" plane through (0, 496.0642, 0) normal (0, 1, 0) x axis (-1, 0, 0)
  line L1 (399.8912, -185) -> (399.8912, -202.5)
  line L2 (379.7049, -185) -> (399.8912, -185)
  line L3 (379.7049, -202.5) -> (379.7049, -185)
  line L4 (399.8912, -202.5) -> (379.7049, -202.5)
  line L5 (379.705, -202.5) -> (399.8912, -202.5)
  line L6 (379.705, -72.5) -> (379.705, -202.5)
  line L7 (399.8912, -72.5) -> (379.705, -72.5)
  line L8 (399.8912, -202.5) -> (399.8912, -72.5)
  point P2 (399.8912, -202.5)
  point P6 (399.8912, -202.5)
  horizontal L5
  vertical L6
  horizontal L7
  vertical L8
  coincident P2 P6
extrude "Extrude14" add sketch "Sketch10" profile of L1 L2 L4 L5 L6 L7 L8 along normal blind 5
extrude "Extrude15" add of existing geometry blind 10
extrude "Extrude16" add of existing geometry blind 10
extrude "Extrude17" add of existing geometry blind 10
sketch "Sketch11" plane through (0, 511.0642, 0) normal (0, 1, 0) x axis (-1, 0, 0)
  line L1 (379.705, -72.5) -> (399.8912, -72.5)
  line L2 (379.705, -202.5) -> (379.705, -72.5)
  line L3 (399.8912, -202.5) -> (379.705, -202.5)
  line L4 (399.8912, -72.5) -> (399.8912, -202.5)
extrude "Extrude18" cut sketch "Sketch11" against normal blind 15
sketch "Sketch12" plane through (0, 496.0642, 0) normal (0, 1, 0) x axis (-1, 0, 0)
  line L1 (379.7049, -72.5) -> (379.705, -72.5)
  line L2 (379.7049, -100) -> (379.7049, -72.5)
  line L3 (399.8912, -100) -> (379.7049, -100)
  line L4 (399.8912, -72.5) -> (399.8912, -100)
  line L5 (379.705, -72.5) -> (399.8912, -72.5)
  line L6 (389.7981, -72.5) -> (389.7981, -100)
  line L7 (399.8912, -86.25) -> (379.7049, -86.25)
  line L8 (397.5962, -98) -> (382, -98)
  line L9 (397.5962, -74.5) -> (397.5962, -98)
  line L10 (382, -74.5) -> (397.5962, -74.5)
  line L11 (382, -98) -> (382, -74.5)
  line L12 (397.5962, -74.5) -> (382, -98)
  line L13 (382, -74.5) -> (397.5962, -98)
  point P7 (389.7981, -100)
  point P8 (389.7981, -72.5)
  point P9 (379.7049, -86.25)
  point P10 (399.8912, -86.25)
  point P15 (389.7981, -86.25)
  midpoint L3 P7
  midpoint L5 P8
  midpoint L2 P9
  midpoint L4 P10
  horizontal L8
  perpendicular L8 L9
  parallel L8 L10
  parallel L9 L11
  coincident L12 P15
  coincident L13 P15
  midpoint L6 P15
extrude "Extrude19" cut sketch "Sketch12" profile of L6 L7 L8 L9 L10 L11 against normal blind 30
sketch "Sketch13" plane through (0, 496.0642, 0) normal (0, 1, 0) x axis (-1, 0, 0)
  line L1 (379.7049, -175) -> (399.8912, -175)
  line L2 (379.7049, -202.5) -> (379.7049, -175)
  line L3 (399.8912, -202.5) -> (379.7049, -202.5)
  line L4 (399.8912, -175) -> (399.8912, -202.5)
  line L5 (399.8912, -188.75) -> (379.7049, -188.75)
  line L6 (389.7981, -202.5) -> (389.7981, -175)
  line L7 (397.5961, -200.5) -> (382.0001, -200.5)
  line L8 (397.5961, -177) -> (397.5961, -200.5)
  line L9 (382.0001, -177) -> (397.5961, -177)
  line L10 (382.0001, -200.5) -> (382.0001, -177)
  line L11 (397.5961, -177) -> (382.0001, -200.5)
  line L12 (382.0001, -177) -> (397.5961, -200.5)
  point P6 (379.7049, -188.75)
  point P7 (399.8912, -188.75)
  point P8 (389.7981, -175)
  point P9 (389.7981, -202.5)
  point P14 (389.7981, -188.75)
  point P12 (397.5961, -177)
  point P13 (382.0001, -177)
  point P11 (397.5961, -200.5)
  midpoint L2 P6
  midpoint L4 P7
  midpoint L1 P8
  midpoint L3 P9
  horizontal L7
  perpendicular L7 L8
  parallel L7 L9
  parallel L8 L10
  coincident L11 P14
  coincident L12 P14
  midpoint L5 P14
  dimension "d192" distance P12 P13 = 15.596
  dimension "d193" distance P11 P12 = 23.5
extrude "Extrude20" cut sketch "Sketch13" profile of L5 L6 L7 L8 L9 L10 against normal blind 35
sketch "Sketch14" plane through (0, 496.0642, 0) normal (0, 1, 0) x axis (-1, 0, 0)
  line L1 (382, -98) -> (397.5962, -98)
  line L2 (382, -74.5) -> (382, -98)
  line L3 (397.5962, -74.5) -> (382, -74.5)
  line L4 (397.5962, -98) -> (397.5962, -74.5)
  line L5 (379.7049, -72.5) -> (379.705, -72.5)
  line L6 (379.7049, -100) -> (379.7049, -72.5)
  line L7 (399.8912, -100) -> (379.7049, -100)
  line L8 (399.8912, -72.5) -> (399.8912, -100)
  line L9 (379.705, -72.5) -> (399.8912, -72.5)
extrude "Extrude21" cut of existing geometry blind -4
extrude "Extrude22" cut sketch "Sketch14" against normal blind 4
work_plane "WorkPlane6" AlongDistance 0
work_plane "WorkPlane7" AlongDistance 0
work_plane "WorkPlane1" AlongDistance 0
sketch "Sketch1" plane through (0, 492.0642, 0) normal (0, 1, 0) x axis (1, 0, 0)
sketch "Sketch11" plane through (0, 492.0642, 0) normal (0, 1, 0) x axis (-1, 0, 0)
  line L1 (382.0001, -200.5) -> (397.5961, -200.5)
  line L2 (382.0001, -177) -> (382.0001, -200.5)
  line L3 (397.5961, -177) -> (382.0001, -177)
  line L4 (397.5961, -200.5) -> (397.5961, -177)
  line L5 (379.7049, -175) -> (399.8912, -175)
  line L6 (379.7049, -202.5) -> (379.7049, -175)
  line L7 (399.8912, -202.5) -> (379.7049, -202.5)
  line L8 (399.8912, -175) -> (399.8912, -202.5)
  line L9 (399.8912, -72.5) -> (379.7, -72.5)
  line L10 (399.8912, -202.5) -> (399.8912, -72.5)
  line L11 (379.7, -202.5) -> (399.8912, -202.5)
  line L12 (379.7, -72.5) -> (379.7, -202.5)
  point P9 (399.8912, -202.5)
  point P12 (399.8912, -202.5)
  horizontal L9
  vertical L10
  horizontal L11
  vertical L12
  coincident P9 P12
extrude "Extrude23" new body sketch "Sketch11" profile of L5 L6 L9 L10 L11 L12 along normal blind 2
extrude "Extrude24" add of existing geometry blind 2
extrude "Extrude25" cut of existing geometry blind -10
chamfer "Chamfer1" distance 10
chamfer "Chamfer2" distance 10
work_plane "WorkPlane2" AlongDistance 0
sketch "Sketch2" plane through (0, 494.0642, 0) normal (0, 1, 0) x axis (1, 0, 0)
  line L1 (-379.7, 202.5) -> (-399.8913, 202.5)
  line L2 (-379.7, 72.5) -> (-379.7, 202.5)
  line L3 (-399.8913, 72.5) -> (-379.7, 72.5)
  line L4 (-399.8913, 202.5) -> (-399.8913, 72.5)
  horizontal L1
  vertical L2
  horizontal L3
  vertical L4
extrude "Extrude1" new body sketch "Sketch2" along normal blind 8
sketch "Sketch3" plane through (0, 494.0642, 0) normal (0, -1, 0) x axis (1, 0, 0)
  line L1 (-399.8913, -202.5) -> (-399.8913, -72.5)
  line L2 (-379.7, -202.5) -> (-399.8913, -202.5)
sketch "Sketch12" plane through (0, 494.0642, 0) normal (0, 1, 0) x axis (-1, 0, 0)
  line L1 (382, -98) -> (397.5962, -98)
  line L2 (382, -74.5) -> (382, -98)
  line L3 (397.5962, -74.5) -> (382, -74.5)
  line L4 (397.5962, -98) -> (397.5962, -74.5)
  line L5 (382.0001, -200.5) -> (397.5961, -200.5)
  line L6 (382.0001, -177) -> (382.0001, -200.5)
  line L7 (397.5961, -177) -> (382.0001, -177)
  line L8 (397.5961, -200.5) -> (397.5961, -177)
  line L9 (399.8912, -202.5) -> (379.7, -202.5)
  line L10 (399.8912, -72.5) -> (399.8912, -202.5)
  line L11 (379.7, -72.5) -> (399.8912, -72.5)
  line L12 (379.7, -202.5) -> (379.7, -72.5)
  line L13 (382, -98) -> (397.5962, -98)
  line L14 (382, -74.5) -> (382, -98)
  line L15 (397.5962, -74.5) -> (382, -74.5)
  line L16 (397.5962, -98) -> (397.5962, -74.5)
  line L17 (397.5961, -177) -> (382.0001, -177)
  line L18 (397.5961, -200.5) -> (397.5961, -177)
  line L19 (382.0001, -200.5) -> (397.5961, -200.5)
  line L20 (382.0001, -177) -> (382.0001, -200.5)
  line L21 (399.8912, -72.5) -> (379.7, -72.5)
  line L22 (399.8912, -202.5) -> (399.8912, -72.5)
  line L23 (379.7, -202.5) -> (399.8912, -202.5)
  line L24 (379.7, -72.5) -> (379.7, -202.5)
  line L25 (397.5961, -173) -> (397.5961, -177)
  line L26 (382, -102) -> (382, -98)
  line L27 (397.5961, -173) -> (397.5961, -102)
  line L28 (382, -102) -> (382, -173)
  line L29 (382, -173) -> (382.0001, -177)
  line L30 (397.5961, -102) -> (397.5962, -98)
  point P4 (382, -74.5)
  point P16 (382, -74.5)
  point P2 (397.5962, -98)
  point P14 (397.5962, -98)
  point P6 (397.5961, -200.5)
  point P20 (397.5961, -200.5)
  point P8 (382.0001, -177)
  point P18 (382.0001, -177)
  point P11 (399.8912, -202.5)
  point P24 (399.8912, -202.5)
  point P13 (379.7, -72.5)
  point P22 (379.7, -72.5)
  point P9 (397.5961, -177)
  point P26 (397.5961, -177)
  point P3 (382, -98)
  point P28 (382, -98)
  point P27 (397.5961, -173)
  point P29 (382, -102)
  horizontal L13
  vertical L14
  horizontal L15
  vertical L16
  coincident P4 P16
  coincident P2 P14
  horizontal L17
  vertical L18
  horizontal L19
  vertical L20
  coincident P6 P20
  coincident P8 P18
  horizontal L21
  vertical L22
  horizontal L23
  vertical L24
  coincident P11 P24
  coincident P13 P22
  coincident P9 P26
  perpendicular L17 L25
  coincident P3 P28
  perpendicular L1 L26
  vertical L27
  vertical L28
  dimension "d214" distance P26 P27 = 4
  dimension "d215" distance P28 P29 = 4
extrude "Extrude26" add sketch "Sketch12" profile of L2 L3 L4 L5 L6 L8 L9 L10 L11 L12 L14 L15 L16 L18 L19 L20 L21 L22 L23 L24 L25 L26 L27 L28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 along normal blind 5
sketch "Sketch15" plane through (0, 494.0642, 0) normal (0, 1, 0) x axis (-1, 0, 0)
  line L1 (397.5962, -98) -> (397.5961, -102)
  line L2 (382, -98) -> (397.5962, -98)
  line L3 (382, -173) -> (382, -98)
  line L4 (382.0001, -177) -> (382, -173)
  line L5 (397.5961, -177) -> (382.0001, -177)
  line L6 (397.5961, -102) -> (397.5961, -177)
  line L7 (382.0931, -98) -> (397.5962, -98)
  line L8 (382.0931, -74.6045) -> (382.0931, -98)
  line L9 (397.5962, -74.6045) -> (382.0931, -74.6045)
  line L10 (397.5962, -98) -> (397.5962, -74.6045)
  line L11 (397.5962, -177) -> (382.0001, -177)
  line L12 (397.5962, -200.453) -> (397.5962, -177)
  line L13 (382.0001, -200.453) -> (397.5962, -200.453)
  line L14 (382.0001, -177) -> (382.0001, -200.453)
  point P3 (397.5962, -98)
  point P8 (397.5962, -98)
  point P6 (382.0001, -177)
  point P12 (382.0001, -177)
  horizontal L7
  vertical L8
  horizontal L9
  vertical L10
  coincident P3 P8
  horizontal L11
  vertical L12
  horizontal L13
  vertical L14
  coincident P6 P12
extrude "Extrude27" cut sketch "Sketch15" profile of L2 L5 L7 L8 L9 L10 L11 L12 L13 L14 along normal blind 7.8
extrude "Extrude3" add of existing geometry blind 1
extrude "Extrude4" add of existing geometry blind 1
sketch "Sketch16" plane through (0, 494.0642, 0) normal (0, -1, 0) x axis (1, 0, 0)
  line L1 (-382.0001, -200.453) -> (-382.0001, -177)
  line L2 (-397.5962, -200.453) -> (-382.0001, -200.453)
  line L3 (-397.5962, -177) -> (-397.5962, -200.453)
  line L4 (-382.0001, -177) -> (-397.5962, -177)
  line L5 (-397.5962, -74.6045) -> (-397.5962, -98)
  line L6 (-382.0931, -74.6045) -> (-397.5962, -74.6045)
  line L7 (-382.0931, -98) -> (-382.0931, -74.6045)
  line L8 (-397.5962, -98) -> (-382.0931, -98)
  line L9 (-399.8913, -72.5) -> (-379.7, -72.5)
  line L10 (-399.8913, -202.5) -> (-399.8913, -72.5)
  line L11 (-379.7, -202.5) -> (-399.8913, -202.5)
  line L12 (-379.7, -72.5) -> (-379.7, -202.5)
  line L13 (-397.5962, -177) -> (-382.0001, -177)
  line L14 (-397.5962, -98) -> (-397.5962, -177)
  line L15 (-382.0001, -98) -> (-397.5962, -98)
  line L16 (-382.0001, -177) -> (-382.0001, -98)
  point P6 (-397.5962, -98)
  point P16 (-397.5962, -98)
  point P2 (-382.0001, -177)
  point P14 (-382.0001, -177)
  horizontal L13
  vertical L14
  horizontal L15
  vertical L16
  coincident P6 P16
  coincident P2 P14
extrude "Extrude5" cut sketch "Sketch16" profile of L4 L8 L13 L14 L15 L16 against normal blind 7.8
extrude "Extrude6" add of existing geometry blind 20
extrude "Extrude7" add of existing geometry blind 20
